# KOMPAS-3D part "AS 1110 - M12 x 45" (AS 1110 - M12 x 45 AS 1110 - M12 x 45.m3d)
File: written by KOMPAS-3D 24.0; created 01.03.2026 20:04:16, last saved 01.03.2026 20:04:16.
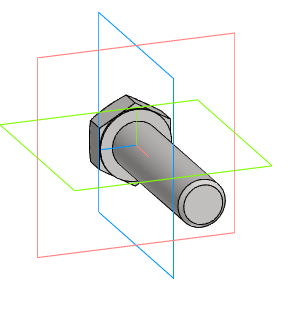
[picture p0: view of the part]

Document properties: Автор: R2D2; Полное имя файла: E:\Работа\Зайцев\GVWR3131M-2W-F-S Задвижка клиновая с выдвижным штоком DN.ru Ду50-200 Ру63\DN80\исходные материалы\AS 1110 - M12 x 45 AS 1110 - M12 x 45.m3d

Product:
- Body: Solid1  | qty 1
- Part/product: AS 1110 - M12 x 45
    Комментарий: Болты и винты   шестигранные точные   метрические ISO
    additional columns: Сталь, мягкая

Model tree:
1. Solid1  (labels: Solid1)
